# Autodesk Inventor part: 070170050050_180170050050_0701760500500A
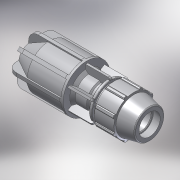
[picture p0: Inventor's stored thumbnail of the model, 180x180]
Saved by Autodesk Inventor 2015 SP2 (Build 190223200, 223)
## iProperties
Created: 2017-02
Part Number: 070170050050_180170050050_0701760500500A
Material: PVC-Piping
Description: PLASSON PLASS4 COUPLING 35-50*50
Document SubType Name: Modeling
Designer: KIM
Mass: 92.6774 g
Surface Area: 199.44 cm^2
Volume: 66.1981 cm^3
Density: 1.4 g/cm^3
Appearance: Smooth - White
Author: KIM
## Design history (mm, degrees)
derived "070170.ipt"
feature "Solid1::070170.ipt"
tag "TaggingFeature1"
body "Solid1"
other parameters: "d4" = 19.28571, "d5" = 32.55, "d7" = 96, "d8" = 62.11198, "d9" = 11.57143, "d11" = 6.75, "d12" = 76.8, "d13" = 120 deg, "d15" = 12 deg, "d16" = 86.4, "d18" = 2.5, "d19" = 35 deg, "d20" = 17.5 deg, "d21" = 89.28, "d23" = 0, "d25" = 360 deg, "d27" = 1.92, "d42" = 41.85, "d43" = 2.88, "d46" = 1.5, "d53" = 1, "d67" = 4.8, "d70" = 45, "d71" = 93, "d74" = 180 deg, "d76" = 121, "d80" = 45, "d84" = 114.95, "d85" = 135 deg, "d86" = 6.05, "d89" = 6.05, "d90" = 135 deg, "d94" = 6.05, "d97" = 7.68, "d98" = 0, "d100" = 360 deg, "d102" = 133.1, "d103" = 24.2, "d104" = 9.68, "d105" = 0, "d110" = 125, "d112" = 162, "d113" = 42.5, "d114" = 108, "d115" = 72.6, "d116" = 162, "d117" = 6.25, "d118" = 48, "d119" = 4.8, "d120" = 0, "d121" = 4.8, "d123" = 360 deg, "E_" = 96, "A_" = 81, "l_" = 93, "E_1" = 121, "l_1" = 125, "d106" = 62.11198
